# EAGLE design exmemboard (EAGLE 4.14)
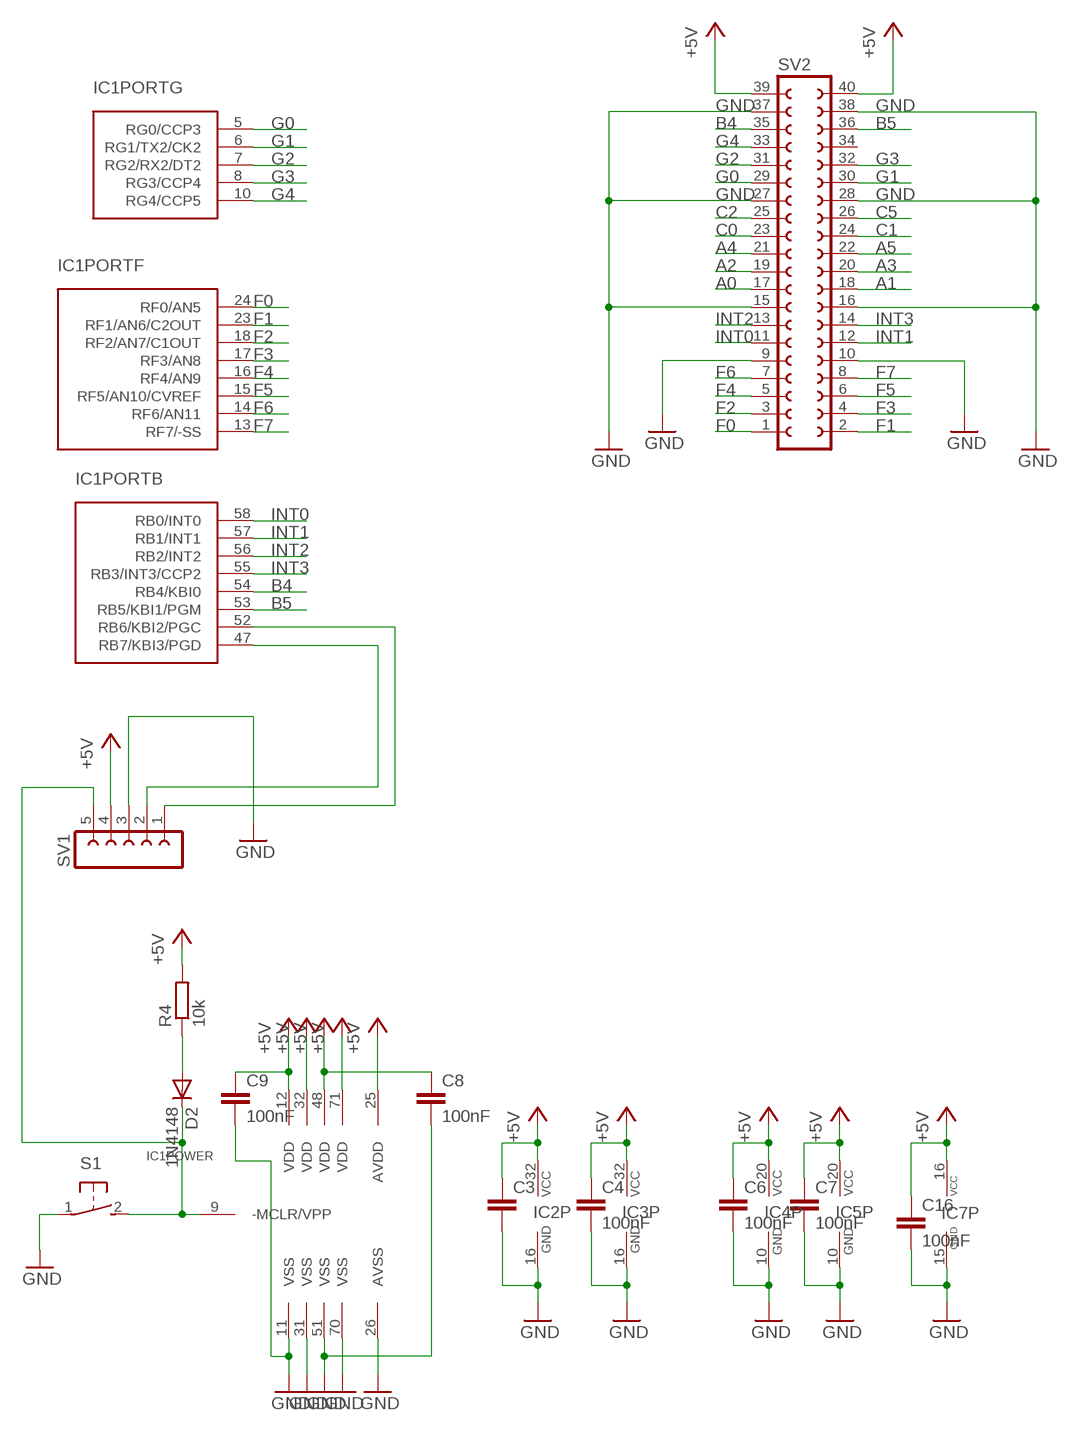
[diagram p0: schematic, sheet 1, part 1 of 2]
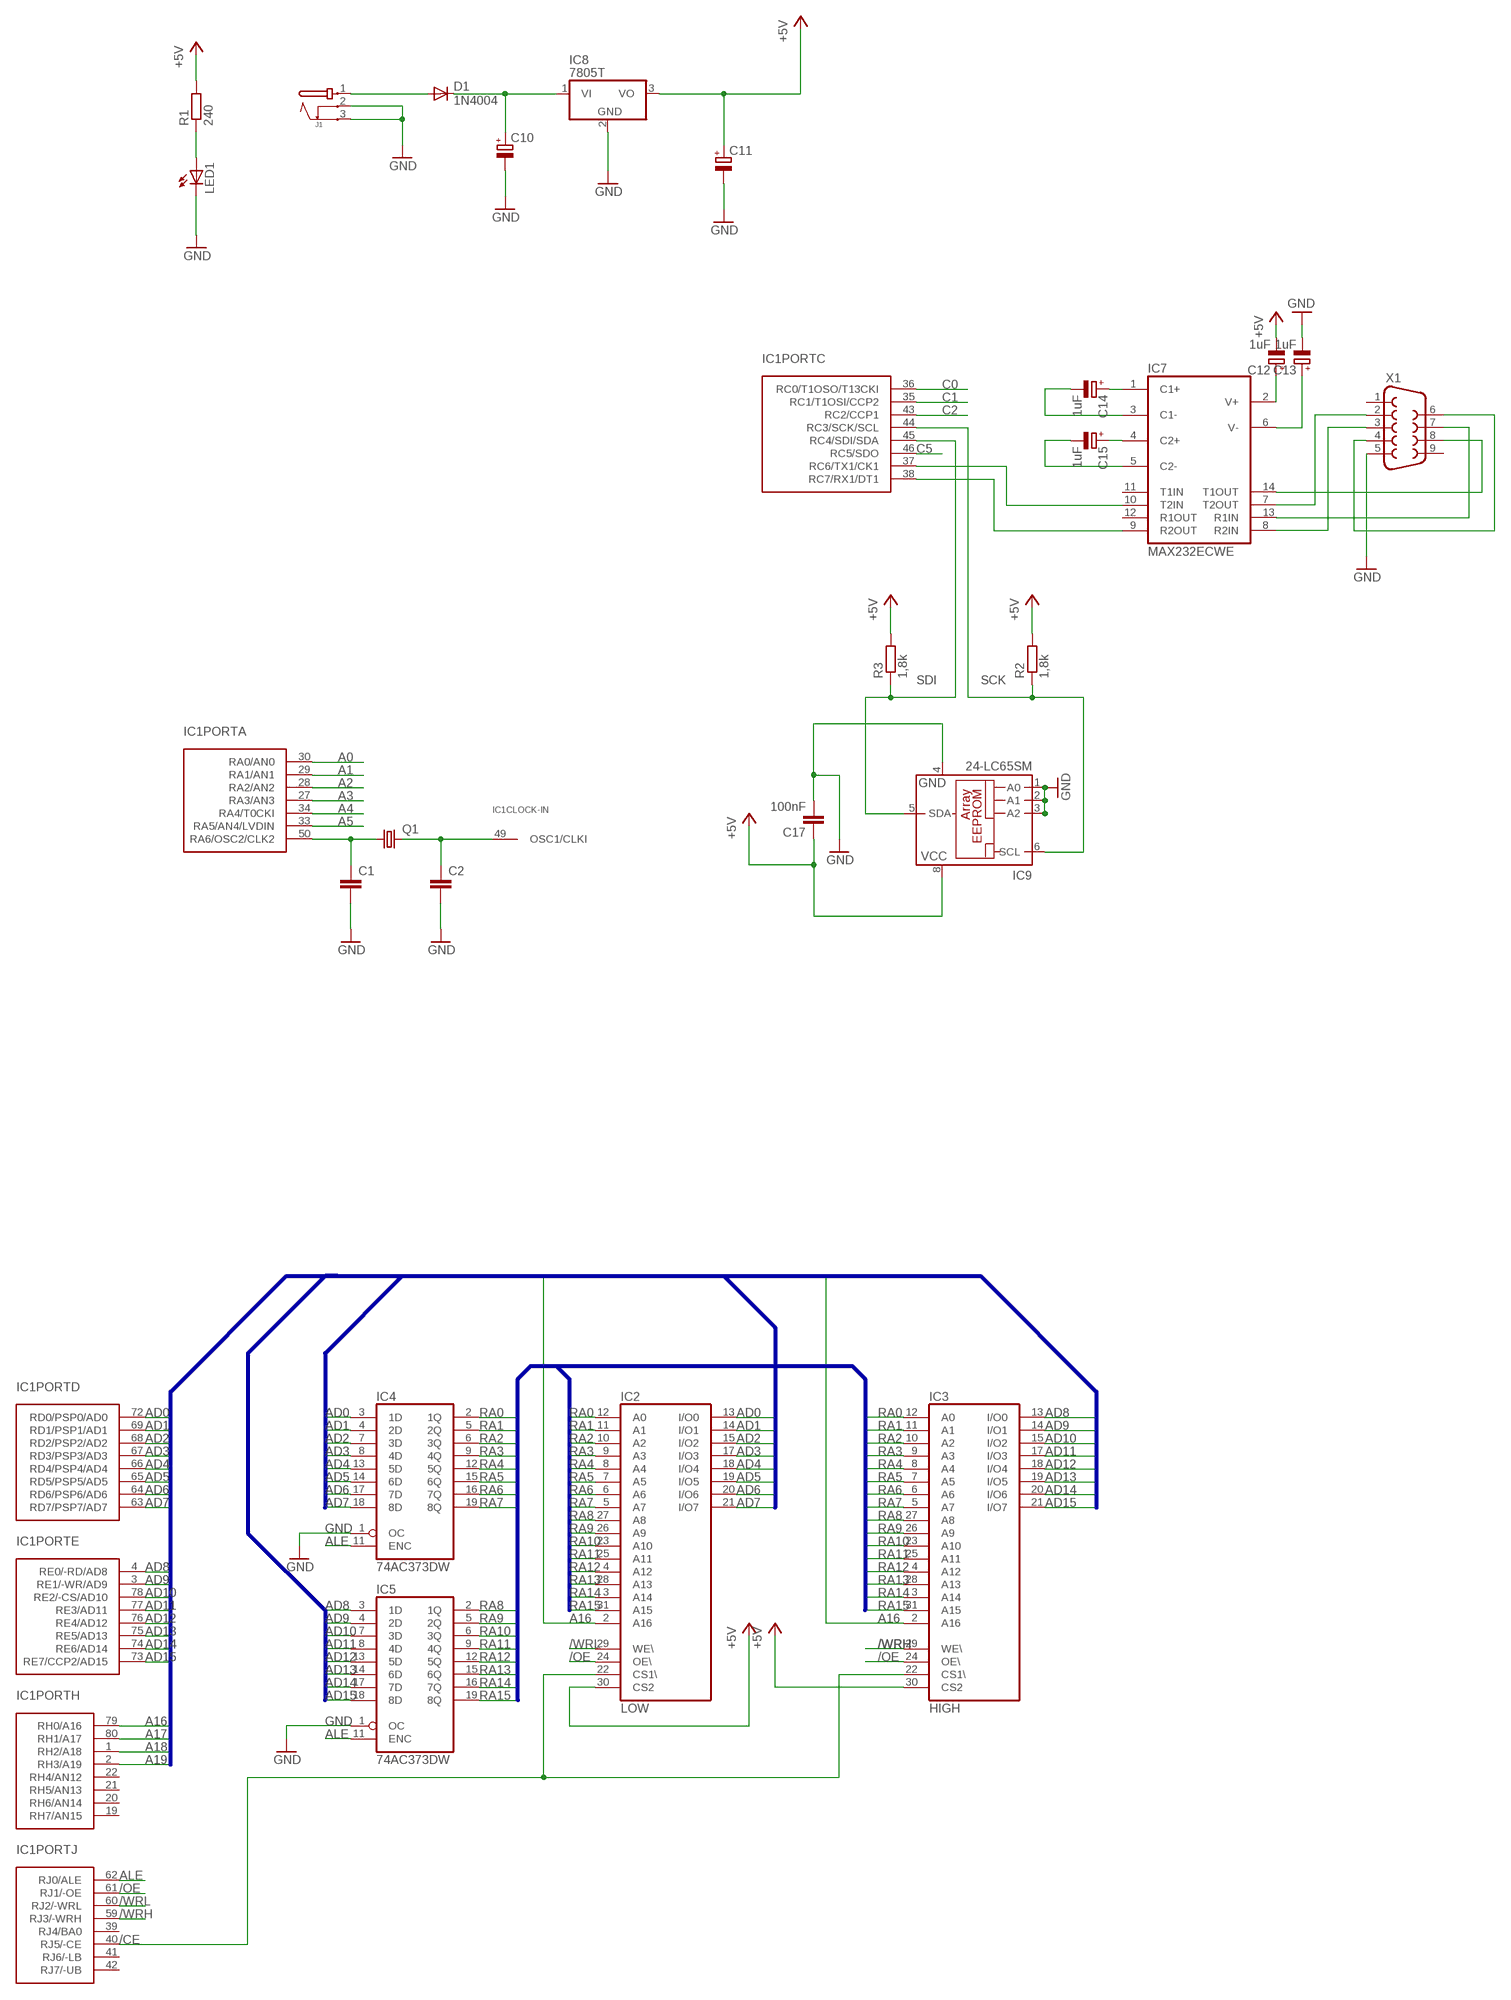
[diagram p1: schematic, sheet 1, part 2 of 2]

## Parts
C1  C-EU025-025X050  [C025-025X050]
C2  C-EU025-025X050  [C025-025X050]
C3  C-EU025-025X050  [C025-025X050]
C4  100nF  C-EU025-025X050  [C025-025X050]
C6  100nF  C-EU025-025X050  [C025-025X050]
C7  100nF  C-EU025-025X050  [C025-025X050]
C8  100nF  C-EU025-025X050  [C025-025X050]
C9  100nF  C-EU025-025X050  [C025-025X050]
C10  CPOL-EUE3.5-8  [E3,5-8]
C11  CPOL-EUE2.5-6  [E2,5-6]
C12  1uF  CPOL-EUE2-4  [E2-4]
C13  1uF  CPOL-EUE2-4  [E2-4]
C14  1uF  CPOL-EUE2-4  [E2-4]
C15  1uF  CPOL-EUE2-4  [E2-4]
C16  100nF  C-EU025-025X050  [C025-025X050]
C17  100nF  C-EU025-025X050  [C025-025X050]
D1  1N4004  [DO41-10]
D2  1N4148  [DO35-10]
IC1  PIC18F8520-I/PT  [TQFP80]
IC2  LOW  LP621024CM  [SOP32L]
IC3  HIGH  LP621024CM  [SOP32L]
IC4  74AC373DW  [SO20W]
IC5  74AC373DW  [SO20W]
IC7  MAX232ECWE  [SO16L]
IC8  7805T  [TO220H]
IC9  24-LC65SM  [SO-08M]
J1  JACK-PMS  [JACK-PMS]
LED1  LED3MM  [LED3MM]
Q1  CRYTALHC49U-V  [HC49U-V]
R1  240  R-EU_R1206  [R1206]
R2  1,8k  R-EU_R1206  [R1206]
R3  1,8k  R-EU_R1206  [R1206]
R4  10k  R-EU_R1206  [R1206]
S1  31-XX  [B3F-31XX]
SV1  FE05-1  [FE05-1]
SV2  FE20-2  [FE20-2]
X1  F09HP  [F09HP]

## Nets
+5V: C3.1 C4.1 C6.1 C7.1 C8.1 C9.1 C11.+ C12.- C16.1 C17.1 IC1.12(POWER:VDD) IC1.25(POWER:AVDD) IC1.32(POWER:VDD) IC1.48(POWER:VDD) IC1.71(POWER:VDD) IC2.30(CS2) IC2.32(VCC) IC3.30(CS2) IC3.32(VCC) IC4.20(VCC) IC5.20(VCC) IC7.16(VCC) IC8.3(VO) IC9.8(VCC) R1.2 R2.2 R3.2 R4.2 SV1.4 SV2.39 SV2.40
/CE: IC1.40(PORTJ:RJ5/-CE) IC2.22(CS1\) IC3.22(CS1\)
/OE: IC1.61(PORTJ:RJ1/-OE) IC2.24(OE\) IC3.24(OE\)
/WRH: IC1.59(PORTJ:RJ3/-WRH) IC3.29(WE\)
/WRL: IC1.60(PORTJ:RJ2/-WRL) IC2.29(WE\)
A0: IC1.30(PORTA:RA0/AN0) SV2.17
A1: IC1.29(PORTA:RA1/AN1) SV2.18
A2: IC1.28(PORTA:RA2/AN2) SV2.19
A3: IC1.27(PORTA:RA3/AN3) SV2.20
A4: IC1.34(PORTA:RA4/T0CKI) SV2.21
A5: IC1.33(PORTA:RA5/AN4/LVDIN) SV2.22
A16: IC1.79(PORTH:RH0/A16) IC2.2(A16) IC3.2(A16)
A17: IC1.80(PORTH:RH1/A17)
A18: IC1.1(PORTH:RH2/A18)
A19: IC1.2(PORTH:RH3/A19)
AD0: IC1.72(PORTD:RD0/PSP0/AD0) IC2.13(I/O0) IC4.3(1D)
AD1: IC1.69(PORTD:RD1/PSP1/AD1) IC2.14(I/O1) IC4.4(2D)
AD2: IC1.68(PORTD:RD2/PSP2/AD2) IC2.15(I/O2) IC4.7(3D)
AD3: IC1.67(PORTD:RD3/PSP3/AD3) IC2.17(I/O3) IC4.8(4D)
AD4: IC1.66(PORTD:RD4/PSP4/AD4) IC2.18(I/O4) IC4.13(5D)
AD5: IC1.65(PORTD:RD5/PSP5/AD5) IC2.19(I/O5) IC4.14(6D)
AD6: IC1.64(PORTD:RD6/PSP6/AD6) IC2.20(I/O6) IC4.17(7D)
AD7: IC1.63(PORTD:RD7/PSP7/AD7) IC2.21(I/O7) IC4.18(8D)
AD8: IC1.4(PORTE:RE0/-RD/AD8) IC3.13(I/O0) IC5.3(1D)
AD9: IC1.3(PORTE:RE1/-WR/AD9) IC3.14(I/O1) IC5.4(2D)
AD10: IC1.78(PORTE:RE2/-CS/AD10) IC3.15(I/O2) IC5.7(3D)
AD11: IC1.77(PORTE:RE3/AD11) IC3.17(I/O3) IC5.8(4D)
AD12: IC1.76(PORTE:RE4/AD12) IC3.18(I/O4) IC5.13(5D)
AD13: IC1.75(PORTE:RE5/AD13) IC3.19(I/O5) IC5.14(6D)
AD14: IC1.74(PORTE:RE6/AD14) IC3.20(I/O6) IC5.17(7D)
AD15: IC1.73(PORTE:RE7/CCP2/AD15) IC3.21(I/O7) IC5.18(8D)
ALE: IC1.62(PORTJ:RJ0/ALE) IC4.11(ENC) IC5.11(ENC)
B4: IC1.54(PORTB:RB4/KBI0) SV2.35
B5: IC1.53(PORTB:RB5/KBI1/PGM) SV2.36
C0: IC1.36(PORTC:RC0/T1OSO/T13CKI) SV2.23
C1: IC1.35(PORTC:RC1/T1OSI/CCP2) SV2.24
C2: IC1.43(PORTC:RC2/CCP1) SV2.25
C5: IC1.46(PORTC:RC5/SDO) SV2.26
F0: IC1.24(PORTF:RF0/AN5) SV2.1
F1: IC1.23(PORTF:RF1/AN6/C2OUT) SV2.2
F2: IC1.18(PORTF:RF2/AN7/C1OUT) SV2.3
F3: IC1.17(PORTF:RF3/AN8) SV2.4
F4: IC1.16(PORTF:RF4/AN9) SV2.5
F5: IC1.15(PORTF:RF5/AN10/CVREF) SV2.6
F6: IC1.14(PORTF:RF6/AN11) SV2.7
F7: IC1.13(PORTF:RF7/-SS) SV2.8
G0: IC1.5(PORTG:RG0/CCP3) SV2.29
G1: IC1.6(PORTG:RG1/TX2/CK2) SV2.30
G2: IC1.7(PORTG:RG2/RX2/DT2) SV2.31
G3: IC1.8(PORTG:RG3/CCP4) SV2.32
G4: IC1.10(PORTG:RG4/CCP5) SV2.33
GND: C1.2 C2.2 C3.2 C4.2 C6.2 C7.2 C8.2 C9.2 C10.- C11.- C13.- C16.2 C17.2 IC1.11(POWER:VSS) IC1.26(POWER:AVSS) IC1.31(POWER:VSS) IC1.51(POWER:VSS) IC1.70(POWER:VSS) IC2.16(GND) IC3.16(GND) IC4.1(OC) IC4.10(GND) IC5.1(OC) IC5.10(GND) IC7.15(GND) IC8.2(GND) IC9.1(A0) IC9.2(A1) IC9.3(A2) IC9.4(GND) J1.2 J1.3 LED1.K(C) S1.1(P) SV1.3 SV2.9 SV2.10 SV2.15 SV2.16 SV2.27 SV2.28 SV2.37 SV2.38 X1.5
INT0: IC1.58(PORTB:RB0/INT0) SV2.11
INT1: IC1.57(PORTB:RB1/INT1) SV2.12
INT2: IC1.56(PORTB:RB2/INT2) SV2.13
INT3: IC1.55(PORTB:RB3/INT3/CCP2) SV2.14
N$2: C1.1 IC1.50(PORTA:RA6/OSC2/CLK2) Q1.1
N$3: C2.1 IC1.49(CLOCK-IN:OSC1/CLKI) Q1.2
N$4: LED1.A R1.1
N$5: C14.+ IC7.1(C1+)
N$6: IC1.38(PORTC:RC7/RX1/DT1) IC7.9(R2OUT)
N$7: IC1.37(PORTC:RC6/TX1/CK1) IC7.10(T2IN)
N$8: IC7.14(T1OUT) X1.8
N$9: IC7.8(R2IN) X1.3
N$10: IC7.7(T2OUT) X1.2
N$11: X1.4 X1.6
N$12: C14.- IC7.3(C1-)
N$13: IC7.13(R1IN) X1.7
N$14: C15.+ IC7.4(C2+)
N$15: C15.- IC7.5(C2-)
N$16: C12.+ IC7.2(V+)
N$17 [+5V]: D1.A J1.1
N$18 [+5V]: C10.+ D1.C IC8.1(VI)
N$19: C13.+ IC7.6(V-)
N$20: D2.A R4.1
N$22: IC1.52(PORTB:RB6/KBI2/PGC) SV1.1
N$23: IC1.47(PORTB:RB7/KBI3/PGD) SV1.2
N$24: D2.C IC1.9(POWER:-MCLR/VPP) S1.2(S) SV1.5
RA0: IC2.12(A0) IC3.12(A0) IC4.2(1Q)
RA1: IC2.11(A1) IC3.11(A1) IC4.5(2Q)
RA2: IC2.10(A2) IC3.10(A2) IC4.6(3Q)
RA3: IC2.9(A3) IC3.9(A3) IC4.9(4Q)
RA4: IC2.8(A4) IC3.8(A4) IC4.12(5Q)
RA5: IC2.7(A5) IC3.7(A5) IC4.15(6Q)
RA6: IC2.6(A6) IC3.6(A6) IC4.16(7Q)
RA7: IC2.5(A7) IC3.5(A7) IC4.19(8Q)
RA8: IC2.27(A8) IC3.27(A8) IC5.2(1Q)
RA9: IC2.26(A9) IC3.26(A9) IC5.5(2Q)
RA10: IC2.23(A10) IC3.23(A10) IC5.6(3Q)
RA11: IC2.25(A11) IC3.25(A11) IC5.9(4Q)
RA12: IC2.4(A12) IC3.4(A12) IC5.12(5Q)
RA13: IC2.28(A13) IC3.28(A13) IC5.15(6Q)
RA14: IC2.3(A14) IC3.3(A14) IC5.16(7Q)
RA15: IC2.31(A15) IC3.31(A15) IC5.19(8Q)
SCK: IC1.44(PORTC:RC3/SCK/SCL) IC9.6(SCL) R2.1
SDI: IC1.45(PORTC:RC4/SDI/SDA) IC9.5(SDA) R3.1
Unconnected: IC1.19(PORTH:RH7/AN15) IC1.20(PORTH:RH6/AN14) IC1.21(PORTH:RH5/AN13) IC1.22(PORTH:RH4/AN12) IC1.39(PORTJ:RJ4/BA0) IC1.41(PORTJ:RJ6/-LB) IC1.42(PORTJ:RJ7/-UB) IC2.1(NC) IC3.1(NC) IC7.11(T1IN) IC7.12(R1OUT) SV2.34 X1.1 X1.9

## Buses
B$1
B$2

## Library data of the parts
C1-C4 C6-C9 C16 C17 = rcl:C-EU: CAPACITOR, European symbol
C10-C15 = rcl:CPOL-EU: POLARIZED CAPACITOR, European symbol
D1 = diode:1N4004: DIODE
D2 = diode:1N4148: DIODE
IC1 = pic18fxx20-fxx8:PIC18F8*20: 80-Pin High Performance, 1 Mbit Enhanced FLASH Microcontrollers with A/D and expansion bus DEVICE DIFFERENCES Feature PIC18F8520 PIC18F8620 PIC18F8720 On-chip Program Memory (Kbytes) 32 64 128 Data Memory (bytes) 2048 3840 3840 Boot Block (bytes) 2048 512 512 Timer1 Low Power Option Yes No No I/O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
IC2 IC3 = memory:LP621024CM: MEMORY
IC4 IC5 = 74xx-eu:74*373: Octal D type transparent LATCH, edge triggered
IC7 = maxim:MAX232ECWE: RS232 TRANSEIVER
IC8 = linear:78*: Positive VOLTAGE REGULATOR Source: http://cache.national.com/ds/LM/LM78L05.pdf http://www.fairchildsemi.com/ds/LM/LM7805.pdf
IC9 = microchip:24-*: Serial EEPROM 32 K/64 K, 1.8 V, I2C
J1 = POWER-IN:JACK-PMS
LED1 = led:LED: LED
Q1 = crystal:CRYTAL: CRYSTAL
R1-R4 = rcl:R-EU_: RESISTOR, European symbol
S1 = switch-omron:31-XX: OMRON SWITCH
SV1 = con-lsta:FE05-1: FEMALE HEADER
SV2 = con-lsta:FE20-2: FEMALE HEADER
X1 = con-subd:F09: SUB-D

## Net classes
0 default: width 0.254 mm
1 +5V: width 0.305 mm

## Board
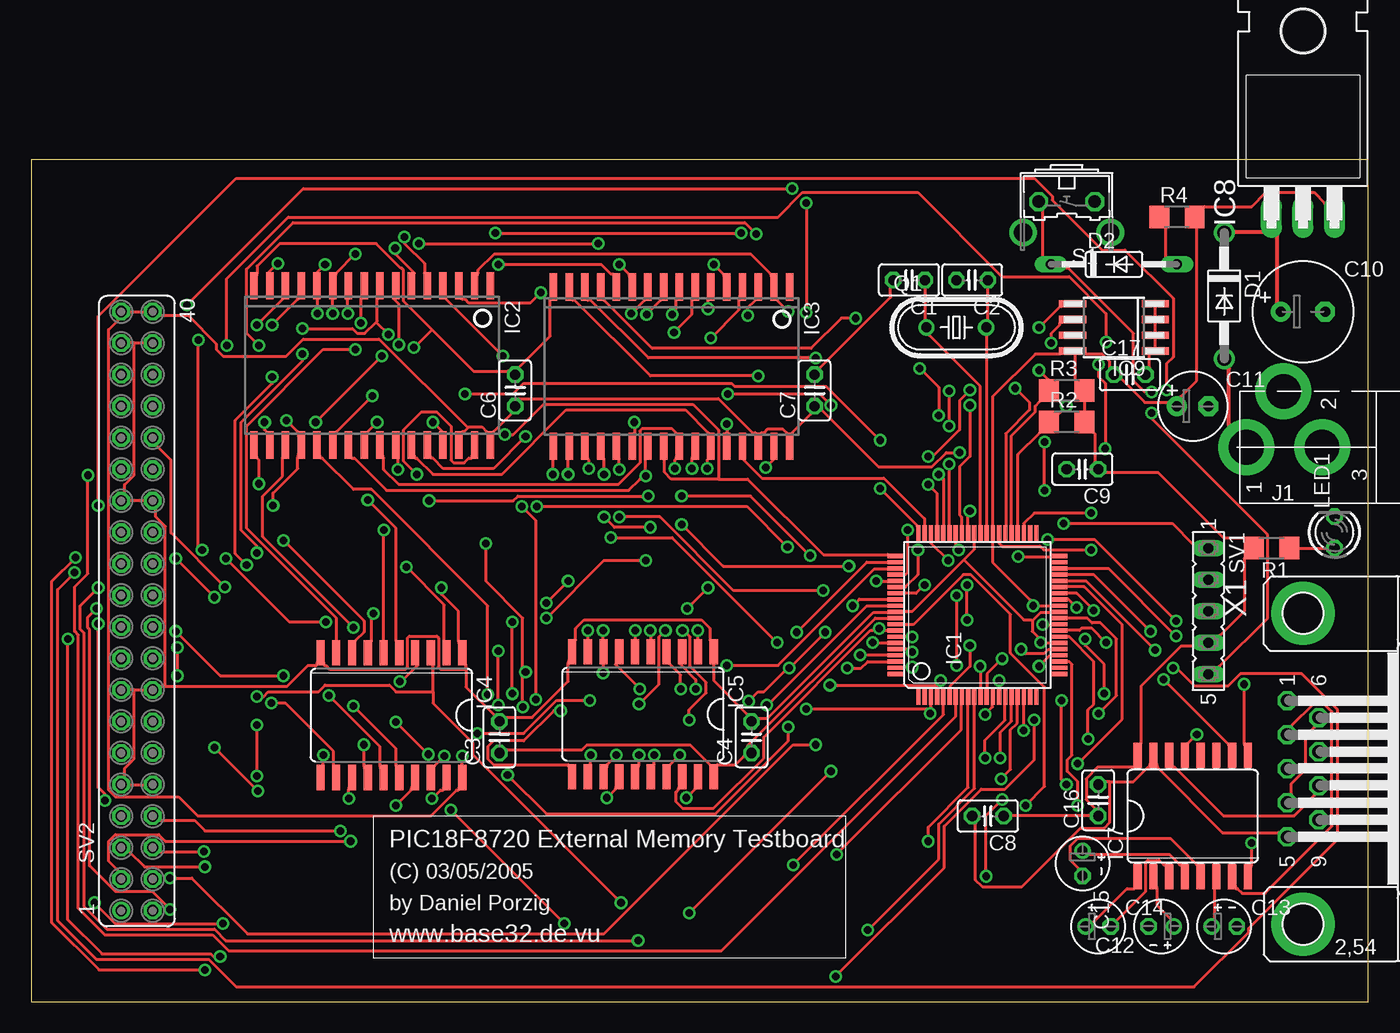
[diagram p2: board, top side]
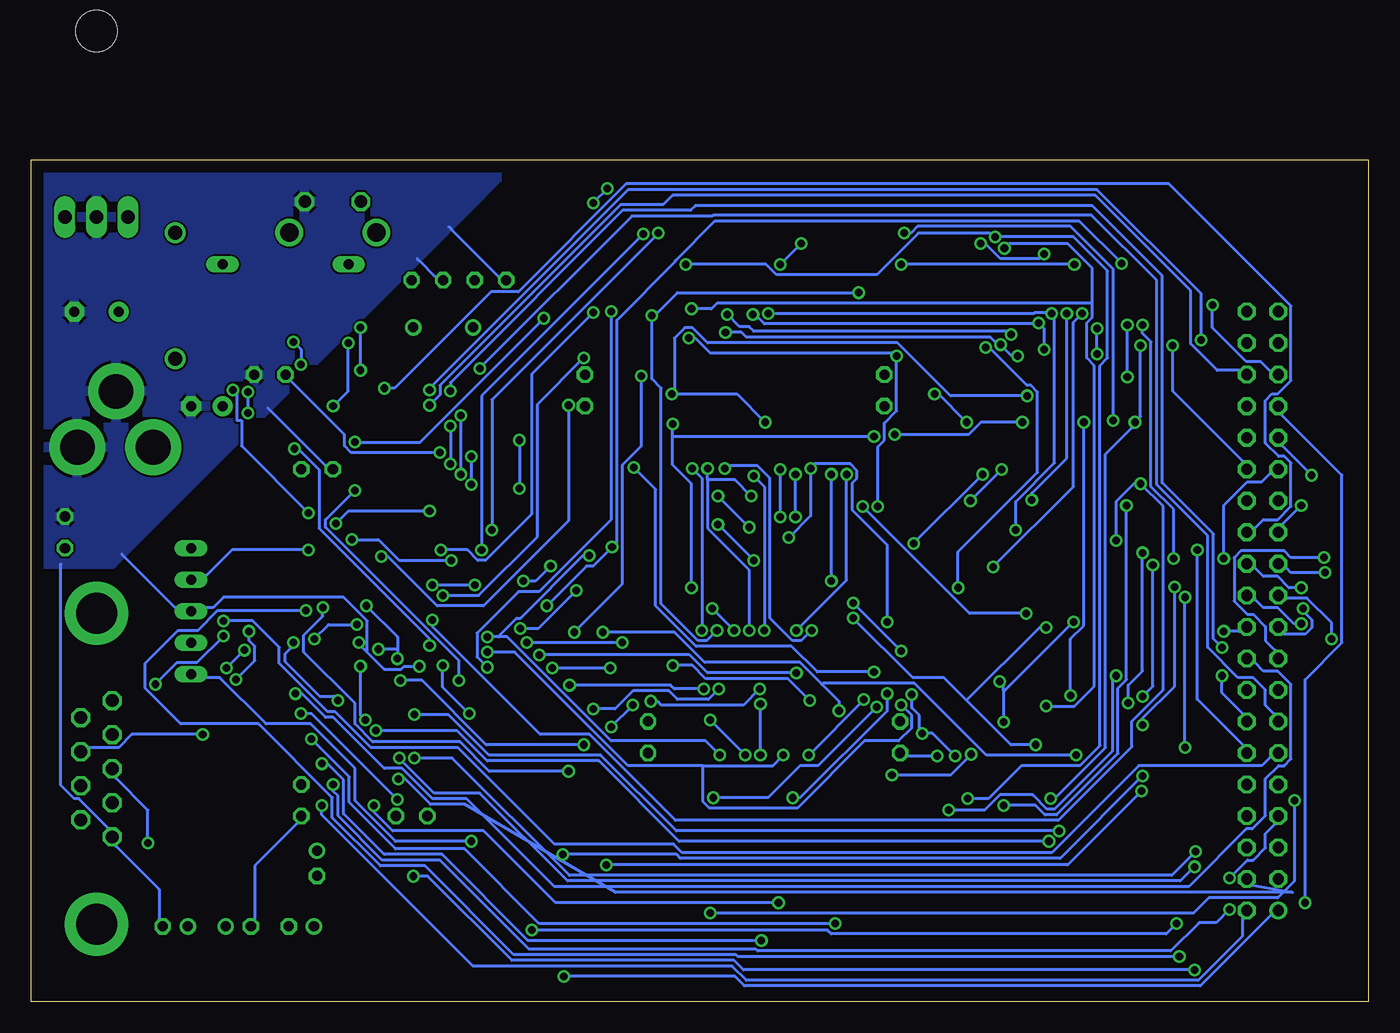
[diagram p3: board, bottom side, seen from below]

Size 107.8 x 67.86 mm. Coordinates in mm from the lower left corner, seen from the top.
Outline: 0,0.02 107.8,0 107.8,67.85 0,67.86 0,0.02
Copper layers (1*16): Top 0.035mm / dielectric 1.5mm / Bottom 0.035mm
Design rules "default": minimum track width 10mil, minimum drill 24mil, track to track 6mil, track to pad 6mil, pad to pad 6mil, via to via 6mil, smd to smd 0mil, copper to edge 40mil, drill to drill 8mil, minimum pad ring 10mil, minimum via ring 8mil, stop-mask expansion 4mil, vias tented up to drill 0mil, thermal gap 10mil

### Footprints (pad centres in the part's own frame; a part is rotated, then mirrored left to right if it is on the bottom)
C025-025X050 = drill 0.813 octagon: 1 -1.27,0; 2 1.27,0
E3,5-8 = drill 0.813 pad 1.6 round: + -1.778,0 | drill 0.813 pad 1.6 octagon: - 1.778,0
E2,5-6 = drill 0.813 pad 1.6 round: + -1.27,0 | drill 0.813 pad 1.6 octagon: - 1.27,0
E2-4 = drill 0.813 pad 1.27 round: + -1.016,0 | drill 0.813 pad 1.27 octagon: - 1.016,0
DO41-10 = drill 1.118 round: A 5.08,0; C -5.08,0
DO35-10 = drill 0.813 long: A 5.08,0; C -5.08,0
TQFP80 = smd 1.3 x 0.35: 1 -6.595,4.75; 2 -6.595,4.25; 3 -6.595,3.75; 4 -6.595,3.25; 5 -6.595,2.75; 6 -6.595,2.25; 7 -6.595,1.75; 8 -6.595,1.25; 9 -6.595,0.75; 10 -6.595,0.25; 11 -6.595,-0.25; 12 -6.595,-0.75; 13 -6.595,-1.25; 14 -6.595,-1.75; 15 -6.595,-2.25; 16 -6.595,-2.75; 17 -6.595,-3.25; 18 -6.595,-3.75; 19 -6.595,-4.25; 20 -6.595,-4.75; 41 6.595,-4.75; 42 6.595,-4.25; 43 6.595,-3.75; 44 6.595,-3.25; 45 6.595,-2.75; 46 6.595,-2.25; 47 6.595,-1.75; 48 6.595,-1.25; 49 6.595,-0.75; 50 6.595,-0.25; 51 6.595,0.25; 52 6.595,0.75; 53 6.595,1.25; 54 6.595,1.75; 55 6.595,2.25; 56 6.595,2.75; 57 6.595,3.25; 58 6.595,3.75; 59 6.595,4.25; 60 6.595,4.75 | smd 0.35 x 1.3: 21 -4.75,-6.595; 22 -4.25,-6.595; 23 -3.75,-6.595; 24 -3.25,-6.595; 25 -2.75,-6.595; 26 -2.25,-6.595; 27 -1.75,-6.595; 28 -1.25,-6.595; 29 -0.75,-6.595; 30 -0.25,-6.595; 31 0.25,-6.595; 32 0.75,-6.595; 33 1.25,-6.595; 34 1.75,-6.595; 35 2.25,-6.595; 36 2.75,-6.595; 37 3.25,-6.595; 38 3.75,-6.595; 39 4.25,-6.595; 40 4.75,-6.595; 61 4.75,6.595; 62 4.25,6.595; 63 3.75,6.595; 64 3.25,6.595; 65 2.75,6.595; 66 2.25,6.595; 67 1.75,6.595; 68 1.25,6.595; 69 0.75,6.595; 70 0.25,6.595; 71 -0.25,6.595; 72 -0.75,6.595; 73 -1.25,6.595; 74 -1.75,6.595; 75 -2.25,6.595; 76 -2.75,6.595; 77 -3.25,6.595; 78 -3.75,6.595; 79 -4.25,6.595; 80 -4.75,6.595
SOP32L = smd 0.6 x 2.2: 1 -9.525,-6.416; 2 -8.255,-6.416; 3 -6.985,-6.416; 4 -5.715,-6.416; 5 -4.445,-6.416; 6 -3.175,-6.416; 7 -1.905,-6.416; 8 -0.635,-6.416; 9 0.635,-6.416; 10 1.905,-6.416; 11 3.175,-6.416; 12 4.445,-6.416; 13 5.715,-6.416; 14 6.985,-6.416; 15 8.255,-6.416; 16 9.525,-6.416; 17 9.525,6.416; 18 8.255,6.416; 19 6.985,6.416; 20 5.715,6.416; 21 4.445,6.416; 22 3.175,6.416; 23 1.905,6.416; 24 0.635,6.416; 25 -0.635,6.416; 26 -1.905,6.416; 27 -3.175,6.416; 28 -4.445,6.416; 29 -5.715,6.416; 30 -6.985,6.416; 31 -8.255,6.416; 32 -9.525,6.416
SO20W = smd 0.66 x 2.032: 1 -5.715,-5.029; 2 -4.445,-5.029; 3 -3.175,-5.029; 4 -1.905,-5.029; 5 -0.635,-5.029; 6 0.635,-5.029; 7 1.905,-5.029; 8 3.175,-5.029; 9 4.445,-5.029; 10 5.715,-5.029; 11 5.715,5.029; 12 4.445,5.029; 13 3.175,5.029; 14 1.905,5.029; 15 0.635,5.029; 16 -0.635,5.029; 17 -1.905,5.029; 18 -3.175,5.029; 19 -4.445,5.029; 20 -5.715,5.029
SO16L = smd 0.66 x 2.032: 1 -4.445,-4.902; 2 -3.175,-4.902; 3 -1.905,-4.902; 4 -0.635,-4.902; 5 0.635,-4.902; 6 1.905,-4.902; 7 3.175,-4.902; 8 4.445,-4.902; 9 4.445,4.902; 10 3.175,4.902; 11 1.905,4.902; 12 0.635,4.902; 13 -0.635,4.902; 14 -1.905,4.902; 15 -3.175,4.902; 16 -4.445,4.902
TO220H = drill 1.118 long: 1 -2.54,-10.16; 2 0,-10.16; 3 2.54,-10.16 | hole 3.302: 0,4.826
SO-08M = smd 0.6 x 2.2: 1 -1.905,-3.33; 2 -0.635,-3.33; 3 0.635,-3.33; 4 1.905,-3.33; 5 1.905,3.33; 6 0.635,3.33; 7 -0.635,3.33; 8 -1.905,3.33
JACK-PMS = drill 2.8 pad 4.5 round: 1 -0.5,-3.31; 2 -5,-0.31; 3 -0.5,2.809
LED3MM = drill 0.813 octagon: A -1.27,0; K 1.27,0
HC49U-V = drill 0.813 round: 1 -2.413,0; 2 2.413,0
R1206 = smd 1.6 x 1.803: 1 -1.422,0; 2 1.422,0
B3F-31XX = drill 1.016 octagon: 1 -2.261,-1.245; 2 2.261,-1.245 | drill 1.499 pad 2.159 round: 3 -3.505,1.245; 4 3.505,1.245
FE05-1 = drill 0.813 long: 1 -5.08,0; 2 -2.54,0; 3 0,0; 4 2.54,0; 5 5.08,0
FE20-2 = drill 0.914 round: 1 -24.13,1.27 | drill 0.914 octagon: 2 -24.13,-1.27; 3 -21.59,1.27; 4 -21.59,-1.27; 5 -19.05,1.27; 6 -19.05,-1.27; 7 -16.51,1.27; 8 -16.51,-1.27; 9 -13.97,1.27; 10 -13.97,-1.27; 11 -11.43,1.27; 12 -11.43,-1.27; 13 -8.89,1.27; 14 -8.89,-1.27; 15 -6.35,1.27; 16 -6.35,-1.27; 17 -3.81,1.27; 18 -3.81,-1.27; 19 -1.27,1.27; 20 -1.27,-1.27; 21 1.27,1.27; 22 1.27,-1.27; 23 3.81,1.27; 24 3.81,-1.27; 25 6.35,1.27; 26 6.35,-1.27; 27 8.89,1.27; 28 8.89,-1.27; 29 11.43,1.27; 30 11.43,-1.27; 31 13.97,1.27; 32 13.97,-1.27; 33 16.51,1.27; 34 16.51,-1.27; 35 19.05,1.27; 36 19.05,-1.27; 37 21.59,1.27; 38 21.59,-1.27; 39 24.13,1.27; 40 24.13,-1.27
F09HP = drill 1.016 octagon: 1 -5.486,-1.27; 2 -2.743,-1.27; 3 0,-1.27; 4 2.743,-1.27; 5 5.486,-1.27; 6 -4.115,1.27; 7 -1.372,1.27; 8 1.372,1.27; 9 4.115,1.27 | drill 3.302 pad 5.08 round: G1 -12.522,0; G2 12.522,0

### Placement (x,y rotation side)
C1  70.77,58.16 180 top
C2  75.85,58.16 180 top
C3  37.75,21.33 90 top
C4  58.07,21.33 90 top
C6  39.02,49.27 90 top
C7  63.15,49.27 90 top
C8  77.12,14.98 180 top
C9  84.74,42.92 180 top
C10  102.52,55.62 0 top
C11  93.63,48 0 top
C12  91.09,6.09 180 top
C13  96.17,6.09 0 top
C14  86.01,6.09 0 top
C15  84.74,11.17 270 top
C16  86.01,16.25 90 top
C17  88.55,50.54 0 top
D1  96.17,56.89 270 top
D2  87.28,59.43 0 top
IC1  76.28,31.17 90 top
IC2  27.49,51.28 180 top
IC3  51.63,51.19 180 top
IC4  29.05,23.1 180 top
IC5  49.32,23.17 180 top
IC7  93.63,14.98 0 top
IC8  102.52,73.4 0 top
IC9  87.28,54.35 90 top
J1  101.25,44.19 270 top
LED1  105.06,37.84 90 top
Q1  74.58,54.35 0 top
R1  99.98,36.57 180 top
R2  83.47,46.73 0 top
R3  83.47,49.27 0 top
R4  92.36,63.24 0 top
S1  83.47,63.24 180 top
SV1  94.9,31.49 270 top
SV2  8.54,31.49 90 top
X1  102.52,18.79 270 top

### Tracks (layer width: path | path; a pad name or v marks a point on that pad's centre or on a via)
+5V  (via drill 0.61)
  Top 0.254: C8.1 79.02,15 85.43,15 C16.1 85.73,15.61 85.04,16.3 85.04,17.97 85.96,18.89 88.93,18.89 IC7.16 89.46,20.87 89.46,25.44 92.66,28.64 93.65,28.64 SV1.4 95.86,29.56 97.77,31.46 97.77,35.73 R1.2 97.77,37.4 96.09,37.4 90.84,42.66 86.64,42.66 C9.1 85.73,43.5 85.73,45.79 85.65,45.86 R2.2 84.89,47.61 84.89,48.38 R3.2 84.13,50.13 84.13,52.19 IC9.8 | v78.26,27.65 77.04,26.43 77.04,25.21 IC1.12 | IC1.32 82.22,31.92 v80.78,31.92 80.55,32.37 77.5,35.42 77.5,37.18 IC1.48 77.5,38.39 77.5,48.76 80.93,52.19 82.91,52.19 IC9.8 | v79.79,28.41 80.09,28.11 81.69,28.11 82,28.41 82.22,28.41 IC1.25 | IC8.3 104.25,64.38 103.41,65.22 99.52,65.22 98.38,64.07 94.57,64.07 R4.2 93.96,62.4 93.96,50.05 92.66,48.76 C11.+ 91.6,48.3 89.77,48.3 87.86,50.21 C17.1 86.95,51.12 86.95,51.58 86.34,52.19 85.04,52.19 IC9.8 | v34.75,19.8 34.75,19.04 IC4.20 34.45,17.06 34.3,17.06 32.24,15 13.42,15 11.89,16.52 6.79,16.52 6.25,17.06 6.25,54.17 7.02,54.93 SV2.39 SV2.40 10.44,55.31 12.65,55.31 14.94,53.02 14.94,52.57 15.47,52.03 20.58,52.03 21.95,53.41 28.05,53.41 35.21,46.24 | IC1.71 69.04,30.93 68.05,30.93 57.76,20.64 C4.1 57.46,19.8 56.77,19.12 55.33,19.12 IC5.20 54.72,19.12 53.12,20.72 44.81,20.72 44.43,20.33 38.33,20.33 C3.1 | 35.21,46.24 35.29,46.32 36.35,46.32 36.73,45.94 IC2.32 37.27,45.94 38.71,47.39 C6.1 39.32,48.61 55.4,48.61 58.15,45.86 58.37,45.86 IC3.30 58.91,45.86 59.06,45.86 59.36,46.17 60.58,46.17 60.89,45.86 IC3.32 61.35,45.86 62.87,47.39 C7.1 63.71,47.69 68.28,43.12 72.62,43.12 73.77,44.26 v74.83,44.26 | 35.21,46.24 34.9,45.94 34.75,45.94 IC2.30
  Bottom 0.254: C12.- 89.77,6.7 89.77,10.96 86.34,14.39 C16.1 | 78.26,28.41 78.26,29.4 v80.78,31.92 | 78.26,28.41 v78.26,27.65 | 78.26,28.41 v79.79,28.41 | v34.75,19.8 37.11,19.8 C3.1 | v74.83,44.26 82,44.26 82.53,44.8 82.53,45.71 86.87,50.05 C17.1
/CE  (via drill 0.61)
  Top 0.254: v79.56,35.88 82.22,35.88 IC1.40 | v64.47,48.07 63.56,48.99 v56.16,48.99 | v48.62,46.7 48.62,45.86 IC3.22 | v27.51,48.83 24.62,45.94 IC2.22
  Bottom 0.254: v79.56,35.88 79.02,35.88 75.06,31.92 71.33,31.92 64.47,38.78 v64.47,48.07 | v48.62,46.7 50.91,48.99 v56.16,48.99 55.94,49.44 55.94,53.48 55.1,54.32 54.49,54.32 53.27,53.1 37.95,53.1 33.69,48.83 v27.51,48.83
/OE  (via drill 0.61)
  Top 0.254: 55.4,42.13 51.59,42.13 51.06,42.66 51.06,43.73 IC3.24 | 55.4,42.13 57.76,42.13 63.86,36.03 69.04,36.03 IC1.61 | v27.89,46.7 27.13,45.94 IC2.24 | v38.18,45.71 38.87,45.71 41.31,48.15 53.35,48.15 55.4,46.09 55.4,42.13
  Bottom 0.254: v27.89,46.7 31.25,46.7 32.24,45.71 v38.18,45.71
/WRH
  Top 0.254: IC1.59 72.01,38.39 72.01,38.93 68.74,42.2 58.91,42.2 57.38,43.73 IC3.29
/WRL  (via drill 0.61)
  Top 0.254: v68.43,41.37 71.4,38.39 IC1.60 | v68.43,45.25 64.09,49.6 56.7,49.6 56.47,49.82 39.71,49.82 38.87,48.99 v34.98,48.99 | v32.39,46.7 33.15,45.94 IC2.29
  Bottom 0.254: v68.43,45.25 v68.43,41.37 | v34.98,48.99 34.68,48.99 v32.39,46.7
A0  (via drill 0.61)
  Top 0.254: v86.03,23.23 87.48,24.68 87.48,29.25 86.19,30.55 85.5,30.55 85.12,30.93 83.52,30.93 IC1.30 | v78.26,16.3 76.97,15 v76.97,10.12 | v14.03,2.58 5.49,2.58 1.68,6.39 1.68,33.9 v3.59,35.8
  Bottom 0.254: v86.03,23.23 85.2,23.23 v78.26,16.3 | v76.97,10.12 75.82,10.12 69.04,3.34 51.14,3.34 50.37,2.58 v14.03,2.58 | v3.59,35.8 6.25,35.8 6.79,36.34 10.29,36.34 10.83,35.8 10.83,32.3 9.76,31.23 9.3,31.23 8.31,30.24 8.31,29.1 7.55,28.34 SV2.17
A1  (via drill 0.61)
  Top 0.254: v81.54,30.39 82.22,30.39 IC1.29 | v84.97,29.25 84.97,28.72 86.49,27.19 v86.49,24.83
  Bottom 0.254: v81.54,30.39 83.83,30.39 v84.97,29.25 | v86.49,24.83 85.96,24.83 84.05,22.93 83.44,22.93 79.33,18.81 77.88,18.81 75.44,16.37 72.7,16.37 65.61,9.29 14.48,9.29 9.83,13.93 9.38,13.93 8.31,15 8.31,17.97 7.24,19.04 6.79,19.04 6.25,19.57 6.25,25.59 7.32,26.66 8.46,26.66 9.15,27.35 SV2.18
A2  (via drill 0.61)
  Top 0.254: v86.64,28.95 85.5,30.09 84.66,30.09 84.51,29.94 83.52,29.94 IC1.28 | v83.06,24.3 83.06,17.9 v83.44,17.52 | v11.21,7.46 9.76,8.9 6.79,8.9 4.73,10.96 4.73,30.01 4.58,30.16 4.58,31 v5.26,31.69
  Bottom 0.254: v86.64,28.95 86.64,28.72 87.33,28.03 87.33,27.42 84.51,24.6 83.37,24.6 v83.06,24.3 | v83.44,17.52 83.44,16.98 83.06,16.6 83.06,15 79.48,11.42 74.83,11.42 67.67,4.26 49.38,4.26 49.23,4.1 15.93,4.1 13.64,6.39 12.27,6.39 v11.21,7.46 | v5.26,31.69 5.26,31.46 4.58,30.77 4.58,30.16 5.11,29.63 6.86,29.63 SV2.19
A3  (via drill 0.61)
  Top 0.254: v85.2,21.17 85.2,23.54 85.65,23.99 85.65,27.42 83.67,29.4 83.52,29.4 IC1.27 | v33.84,15.46 v42.98,6.31 | v20.35,26.28 15.25,26.28 v11.66,29.86
  Bottom 0.254: v85.2,21.17 82.15,18.13 82.15,16.07 78.41,12.33 72.85,12.33 66.83,6.31 v42.98,6.31 | v33.84,15.46 30.94,15.46 29.72,16.68 27.06,16.68 25.91,15.53 25.3,15.53 20.66,20.18 20.66,25.97 v20.35,26.28 | v11.66,29.86 10.44,29.86 SV2.20
A4  (via drill 0.61)
  Top 0.254: v85.65,31.54 84.28,32.91 83.52,32.91 IC1.34 | v15.25,3.65 14.71,3.65 14.48,3.88 5.72,3.88 2.98,6.62 v2.98,29.25
  Bottom 0.254: v85.65,31.54 92.74,31.54 94.34,29.94 95.94,29.94 98.61,27.27 98.61,25.29 95.71,22.39 89.46,22.39 83.52,16.45 83.52,14.85 79.63,10.96 76.05,10.96 68.89,3.8 50.98,3.8 50.83,3.65 v15.25,3.65 | v2.98,29.25 2.98,30.55 4.96,32.53 6.63,32.53 SV2.21
A5  (via drill 0.61)
  Top 0.254: v84.28,31.76 83.6,32.45 83.52,32.45 IC1.33 | v53.04,7.15 v64.47,18.58 | v5.95,16.22 5.95,16.75 5.42,17.29 v5.42,30.47
  Bottom 0.254: v84.28,31.76 84.28,31.08 85.81,29.56 85.81,28.18 81.69,24.07 81.69,22.39 80.24,20.94 73.23,20.94 70.87,18.58 v64.47,18.58 | v53.04,7.15 14.1,7.15 12.88,8.37 7.32,8.37 5.95,9.74 v5.95,16.22 | v5.42,30.47 6.02,30.47 7.32,31.76 8.46,31.76 9.15,32.45 SV2.22
A16  (via drill 0.61)
  Top 0.254: v71.02,26.96 70.26,26.96 IC1.79 | v61.04,55.62 60.13,56.53 IC3.2 59.59,58.66 57.99,60.26 37.34,60.26 36.05,58.97 36.05,58.74 IC2.2
  Bottom 0.254: v71.02,26.96 71.86,27.8 71.86,29.71 68.51,33.06 66.83,33.06 61.04,38.85 v61.04,55.62
AD0  (via drill 0.61)
  Top 0.254: v80.17,15.84 81.69,17.36 81.69,25.36 78.95,28.11 78.95,31.23 75.75,34.43 75.14,34.43 71.1,30.39 70.26,30.39 IC1.72 | v47.55,7.99 35.59,19.95 35.59,20.87 32.39,24.07 32.39,24.98 | 32.39,24.98 32.39,27.12 IC4.3 | v19.44,54.55 21.49,56.61 IC2.13 | v19.44,50.36 19.44,49.82 16.46,46.85 16.46,36.11 v17.38,35.19 | v18.22,24.6 18.75,24.6 19.13,24.98 23.17,24.98 23.7,25.52 28.88,25.52 29.42,24.98 32.39,24.98
  Bottom 0.254: v80.17,15.84 80.17,15.31 78.64,13.78 71.33,13.78 65.54,7.99 v47.55,7.99 | v19.44,50.36 v19.44,54.55 | v17.38,35.19 17.38,25.44 v18.22,24.6
AD1  (via drill 0.61)
  Top 0.254: v59.29,23.92 59.36,23.92 67.37,31.92 69.04,31.92 IC1.69 | v61.04,22.16 61.04,21.02 55.17,15.15 41.53,15.15 v38.41,18.28 | v29.42,22.54 v32.01,19.95 | v29.72,25.82 29.88,25.82 31.17,27.12 IC4.4 | v18.22,54.55 20.27,56.61 IC2.14 | v15.7,35.73 20.81,30.62 v23.78,30.62
  Bottom 0.254: v61.04,22.16 v59.29,23.92 | v38.41,18.28 33.69,18.28 v32.01,19.95 | 29.42,25.06 29.42,25.52 v29.72,25.82 | 29.42,25.06 v29.42,22.54 | v18.22,54.55 18.22,53.86 17.53,53.18 17.53,41.52 15.7,39.69 v15.7,35.73 | v23.78,30.62 29.34,25.06 29.42,25.06
AD2  (via drill 0.61)
  Top 0.254: v66.22,31.92 66.76,32.45 69.04,32.45 IC1.68 | v19.89,59.5 19.13,58.74 IC2.15 | v27.59,31.31 27.44,31.16 27.44,29.1 IC4.7 | v40.77,39.92 57.69,39.92 v60.97,36.64
  Bottom 0.254: v66.22,31.92 63.02,35.12 62.49,35.12 v60.97,36.64 60.58,37.02 60.58,54.93 55.86,59.65 55.86,59.73 52.66,62.93 23.32,62.93 v19.89,59.5 | v27.59,31.31 32.16,31.31 v40.77,39.92
AD3  (via drill 0.61)
  Top 0.254: v72.01,33.59 71.33,32.91 70.26,32.91 IC1.67 | v75.44,30.77 v75.44,33.59 | v18.37,41.75 18.37,43.65 18.22,43.8 IC2.17 | v20.35,37.18 26.83,30.7 26.83,29.78 26.14,29.1 IC4.8
  Bottom 0.254: v75.44,33.59 v72.01,33.59 | v75.44,30.77 75.44,30.24 66.76,21.55 62.79,21.55 55.86,14.62 25,14.62 19.06,20.56 19.06,22.62 16.54,25.14 16.54,39.92 v18.37,41.75 18.83,41.82 20.35,40.3 v20.35,37.18
AD4  (via drill 0.61)
  Top 0.254: v71.48,36.41 71.48,34.43 70.49,33.44 70.26,33.44 IC1.66 | v58.45,61.86 57.54,62.78 21.11,62.78 17.38,59.04 17.38,53.86 v18.37,52.87 | v18.83,46.7 18.83,46.09 18.98,45.94 IC2.18 | v25.61,16.37 25.61,17.06 IC4.13
  Bottom 0.254: v71.48,36.41 71.48,48.83 v58.45,61.86 | v18.37,52.87 18.37,47.16 v18.83,46.7 19.06,46.24 21.19,44.11 21.19,20.49 25.3,16.37 v25.61,16.37
AD5  (via drill 0.61)
  Top 0.254: v68.13,33.9 69.04,33.9 IC1.65 | v65.92,35.12 55.78,35.12 v52.43,38.47 | v49.54,35.57 46.18,35.57 v41.53,30.93 | v26.83,20.72 26.83,19.04 IC4.14 | v25.99,30.16 18.67,37.48 18.67,40.76 20.27,42.36 20.27,43.8 IC2.19
  Bottom 0.254: v68.13,33.9 67.14,33.9 v65.92,35.12 | v49.54,35.57 v52.43,38.47 | v41.53,30.93 36.73,26.13 34.22,26.13 32.39,24.3 | 32.39,24.3 28.81,20.72 v26.83,20.72 | v25.99,30.16 26.52,30.16 32.39,24.3
AD6  (via drill 0.61)
  Top 0.254: v70.64,38.01 70.64,34.58 70.49,34.43 70.26,34.43 IC1.64 | v37.42,61.94 v57.23,61.94 | v20.58,46.85 21.49,45.94 IC2.20 21.49,43.8 21.49,42.97 19.51,40.99 v19.51,39.99 | v29.42,15.84 30.64,17.06 IC4.17
  Bottom 0.254: v70.64,38.01 70.64,48.53 v57.23,61.94 | v37.42,61.94 36.89,61.94 36.35,62.47 24.01,62.47 20.58,59.04 v20.58,46.85 | v29.42,15.84 26.83,15.84 26.07,15.08 25.15,15.08 20.2,20.03 20.2,25.29 19.51,25.97 v19.51,39.99
AD7  (via drill 0.61)
  Top 0.254: v56.09,27.12 60.2,27.12 67.98,34.89 69.04,34.89 IC1.63 | v45.04,24.3 42.37,24.3 39.71,21.63 v35.97,21.63 | v33.3,19.8 32.54,19.04 IC4.18 | v36.81,24.75 36.81,31.92 27.44,41.29 25.99,41.29 23.47,43.8 23.32,43.8 IC2.21
  Bottom 0.254: v56.09,27.12 54.49,27.12 53.42,26.05 46.79,26.05 v45.04,24.3 | v33.3,19.8 35.13,21.63 v35.97,21.63 36.2,22.09 36.2,23.08 36.81,23.69 v36.81,24.75
AD8  (via drill 0.61)
  Top 0.254: 72.93,25.52 73,25.44 73,25.21 IC1.4 | v64.39,25.52 72.93,25.52 | v53.57,25.21 53.57,25.97 52.35,27.19 IC5.3 | v66.45,55.08 65.31,55.08 62.87,52.64 50.07,52.64 46.18,56.53 IC3.13 | v81.69,41.21 v81.69,45.1 | 72.93,25.52 v73.31,25.9
  Bottom 0.254: v64.39,25.52 56.24,25.52 55.94,25.21 v53.57,25.21 | v66.45,55.08 76.43,45.1 v81.69,45.1 | v81.69,41.21 84.05,38.85 84.05,38.24 73.31,27.5 v73.31,25.9
AD9  (via drill 0.61)
  Top 0.254: 72.4,23.61 72.55,23.76 72.55,23.99 IC1.3 | v62.49,23.61 72.4,23.61 | v52.35,25.21 52.35,26.35 51.52,27.19 IC5.4 | v63.25,51.88 49.76,51.88 45.12,56.53 44.89,56.53 IC3.14 | v74.6,27.12 v74.6,32.76 | v72.47,23.23 72.47,23.54 72.4,23.61
  Bottom 0.254: v62.49,23.61 60.74,23.61 59.29,25.06 56.39,25.06 55.71,24.37 53.19,24.37 v52.35,25.21 | v63.25,51.88 66.98,48.15 66.98,37.48 71.71,32.76 v74.6,32.76 | v74.6,27.12 74.6,25.36 v72.47,23.23
AD10  (via drill 0.61)
  Top 0.254: v65.77,26.89 66.91,26.89 67.44,27.42 69.04,27.42 IC1.78 | v57.84,24.22 58.6,24.98 59.06,24.98 60.97,26.89 v61.12,26.89 v64.01,29.78 | v49.08,25.21 47.1,27.19 IC5.7 | v58.6,50.43 49.92,50.43 43.82,56.53 43.67,56.53 IC3.15
  Bottom 0.254: v61.12,26.89 v65.77,26.89 | v57.84,24.22 57.31,24.22 57,23.92 50.37,23.92 v49.08,25.21 | v58.6,50.43 58.6,44.8 60.13,43.27 60.13,33.67 v64.01,29.78
AD11  (via drill 0.61)
  Top 0.254: v66.83,27.95 69.04,27.95 IC1.77 | v46.11,26.51 46.11,27.19 IC5.8 46.11,29.17 v46.11,29.94 | v42.07,42.51 42.07,43.73 IC3.17
  Bottom 0.254: v66.83,27.95 54.72,27.95 53.27,26.51 v46.11,26.51 | v42.07,42.51 42.07,33.97 v46.11,29.94
AD12  (via drill 0.61)
  Top 0.254: v71.02,28.18 70.79,28.41 70.26,28.41 IC1.76 | v47.17,19.88 46.41,19.12 IC5.13 | v43.29,42.51 43.29,43.73 IC3.18 | v41.53,32.15 v43.29,33.9 | v37.65,23.92 v37.65,28.26
  Bottom 0.254: v71.02,28.18 68.81,28.18 59.67,19.04 53.65,19.04 | 53.65,19.04 48.01,19.04 v47.17,19.88 | v43.29,33.9 v43.29,42.51 | v37.65,28.26 v41.53,32.15 | v37.65,23.92 36.81,23.08 36.81,22.09 37.88,21.02 40.62,21.02 46.03,15.61 53.12,15.61 53.65,16.14 53.65,19.04
AD13  (via drill 0.61)
  Top 0.254: v67.82,28.95 69.04,28.95 IC1.75 | v60.13,28.95 51.67,37.4 v46.72,37.4 | v44.96,42.97 44.96,43.65 44.89,43.73 IC3.19 | v46.41,16.45 47.1,17.13 IC5.14 | v38.79,24.83 v38.79,30.62
  Bottom 0.254: v60.13,28.95 v67.82,28.95 | v46.72,37.4 44.96,39.16 v44.96,42.97 44.66,43.35 41.76,43.35 41.23,42.81 41.23,42.2 41.61,41.82 41.61,39.61 38.79,36.79 v38.79,30.62 | v46.41,16.45 45.8,16.45 38.79,23.46 v38.79,24.83
AD14  (via drill 0.61)
  Top 0.254: v71.02,29.4 70.26,29.4 IC1.74 | v52.28,19.88 51.52,19.12 IC5.17 | v46.18,42.51 46.18,43.73 IC3.20 | v46.18,39.08 47.02,38.24 v49.92,38.24 | v52.43,40.76 57.99,40.76 v62.79,35.96
  Bottom 0.254: 70.11,29.4 69.42,29.4 61.04,21.02 53.42,21.02 v52.28,19.88 | 70.11,29.4 v71.02,29.4 | v46.18,39.08 v46.18,42.51 | v52.43,40.76 v49.92,38.24 | v62.79,35.96 63.33,35.96 68.36,30.93 68.66,30.93 70.11,29.48 70.11,29.4
AD15  (via drill 0.61)
  Top 0.254: 68.36,29.94 67.67,29.94 59.06,21.33 59.06,19.65 55.02,15.61 52.51,15.61 51.97,16.14 51.97,16.91 52.2,17.13 IC5.18 | 68.36,29.94 69.04,29.94 IC1.73 | v47.4,42.89 47.4,43.73 IC3.21 | v47.4,39.08 50.68,39.08 56.62,33.14 v63.86,33.14 | 68.36,29.94 v68.36,30.09
  Bottom 0.254: v47.4,39.08 v47.4,42.89 | v63.86,33.14 66.91,30.09 v68.36,30.09
ALE  (via drill 0.61)
  Top 0.254: v61.73,29.78 67.37,35.42 69.04,35.42 IC1.62 | v42.68,23.46 42.14,23.46 39.71,21.02 37.27,21.02 36.81,20.56 36.81,19.57 37.27,19.12 43.29,19.12 IC5.11 | v23.55,19.88 23.55,19.04 IC4.11
  Bottom 0.254: v61.73,29.78 55.94,29.78 53.5,27.35 45.8,27.35 44.05,25.59 | 44.05,25.59 42.68,24.22 v42.68,23.46 | v23.55,19.88 30.79,19.88 36.58,25.67 43.97,25.67 44.05,25.59
B4  (via drill 0.61)
  Top 0.254: v74.76,36.41 74.53,36.64 74.53,37.18 IC1.54 | v62.49,64.38 v62.49,55.54 | v61.35,65.52 21.95,65.52 v12.58,56.15
  Bottom 0.254: v74.76,36.41 72.62,36.41 71.79,35.57 71.18,35.57 67.44,39.31 67.44,50.59 v62.49,55.54 | v61.35,65.52 v62.49,64.38 | v12.58,56.15 12.58,54.32 9.83,51.58 8.69,51.58 7.93,50.81 SV2.35
B5  (via drill 0.61)
  Top 0.254: v75.67,48.07 75.67,43.96 74.83,43.12 74.83,39.23 74.99,39.08 74.99,38.39 IC1.53
  Bottom 0.254: v75.67,48.07 74.83,48.91 74.83,49.67 60.28,64.23 56.85,64.23 56.09,64.99 22.03,64.99 14.33,57.29 14.33,53.02 12.2,50.89 10.44,50.89 SV2.36
C0  (via drill 0.61)
  Top 0.254: v90.61,28.34 85.04,33.9 83.52,33.9 IC1.36 | v92.05,26.89 92.36,26.89 93.81,25.44 96.47,25.44 97.46,26.43 102.42,26.43 105.31,23.54 105.31,13.1 98.15,5.93 98.15,5.63 93.73,1.21 16.54,1.21 14.33,3.42 5.26,3.42 2.14,6.54 2.14,33.21 v3.51,34.58
  Bottom 0.254: v92.05,26.89 v90.61,28.34 | v3.51,34.58 6.25,34.58 6.63,34.97 SV2.23
C1  (via drill 0.61)
  Top 0.254: v84.36,19.19 87.94,22.77 87.94,30.39 84.89,33.44 83.52,33.44 IC1.35 | v48.93,4.94 15.7,4.94 14.79,5.86 6.1,5.86 4.27,7.69 4.27,29.71 3.97,30.01 3.97,31.92 v5.42,33.37
  Bottom 0.254: v84.36,19.19 83.9,19.19 82.61,17.9 82.61,15.15 79.33,11.88 74.68,11.88 67.75,4.94 v48.93,4.94 | v5.42,33.37 6.41,33.37 7.32,34.28 8.46,34.28 9.15,34.97 SV2.24
C2  (via drill 0.61)
  Top 0.254: v85.43,39.38 80.85,39.38 80.02,38.55 80.02,38.39 IC1.43 | v91.52,49.29 91.52,51.42 92.05,51.96 92.05,56.68 88.17,60.57 86.34,60.57 82.3,64.61 82.3,64.91 80.85,66.36 16.54,66.36 5.42,55.23 v5.42,39.99
  Bottom 0.254: v85.43,39.38 90.84,44.8 90.84,46.85 91.22,46.85 91.22,49.29 v91.52,49.29 | v5.42,39.99 6.94,38.47 SV2.25
C5  (via drill 0.61)
  Top 0.254: v79.33,49.44 80.47,48.3 80.47,47.69 78.57,45.79 78.57,38.39 IC1.46
  Bottom 0.254: v79.33,49.44 78.49,49.44 70.72,57.22 68.51,57.22 59.82,65.9 16.08,65.9 6.25,56.07 6.25,50.05 7.32,48.99 7.78,48.99 8.31,48.45 8.31,45.02 7.24,43.96 6.79,43.96 6.25,43.42 6.25,39.92 7.32,38.85 8.46,38.85 9.15,38.17 SV2.26
F0  (via drill 0.61)
  Top 0.254: v81.23,27.04 82.07,27.88 82.22,27.88 IC1.24 | v80.85,22.7 80.85,19.5 78.49,17.13 76.59,17.13 73.61,14.16 73.61,10.81 v64.85,2.05
  Bottom 0.254: v81.23,27.04 81.23,23.08 v80.85,22.7 | v64.85,2.05 51.06,2.05 50.3,1.28 13.57,1.28 7.85,7 SV2.1
F1  (via drill 0.61)
  Top 0.254: v84.36,15.84 84.36,17.74 83.52,18.58 83.52,19.5 83.9,19.88 83.9,27.19 83.67,27.42 83.52,27.42 IC1.23
  Bottom 0.254: v84.36,15.84 84.36,15.08 72.17,2.89 51.29,2.89 50.14,1.74 13.72,1.74 10.14,5.32 10.14,6.7 SV2.2
F2  (via drill 0.61)
  Top 0.254: v80.02,21.86 80.02,23.99 IC1.18 | v25.76,12.94 10.83,12.94 10.29,13.48 6.79,13.48 6.25,12.94 6.25,11.34 7.02,10.58 SV2.3
  Bottom 0.254: v80.02,21.86 73.46,21.86 71.02,19.42 62.03,19.42 55.55,12.94 v25.76,12.94
F3  (via drill 0.61)
  Top 0.254: v78.19,17.97 78.95,18.73 78.95,21.94 79.48,22.47 79.48,23.99 IC1.17
  Bottom 0.254: v78.19,17.97 77.65,17.97 75.6,15.92 72.85,15.92 60.69,8.83 6.13,8.83 10.44,9.59 SV2.4
F4  (via drill 0.61)
  Top 0.254: v78.11,19.65 78.11,21.71 79.02,22.62 79.02,23.99 IC1.16 | v14.03,10.89 9.15,10.89 7.93,12.11 SV2.5
  Bottom 0.254: v78.11,19.65 75.29,16.83 71.63,16.83 64.55,9.74 15.17,9.74 v14.03,10.89
F5  (via drill 0.61)
  Top 0.254: v76.89,19.65 76.89,21.1 78.49,22.7 78.49,23.99 IC1.15 | v13.95,12.11 10.44,12.11 SV2.6
  Bottom 0.254: v76.89,19.65 73.84,19.65 64.39,10.2 15.85,10.2 v13.95,12.11
F6  (via drill 0.61)
  Top 0.254: v78.03,25.9 78.03,25.21 IC1.14 | v63.25,20.72 61.42,20.72 46.18,5.48 17.45,5.48 12.96,9.97 v11.21,9.97
  Bottom 0.254: v78.03,25.9 76.28,25.9 71.1,20.72 v63.25,20.72 | v11.21,9.97 9.76,11.42 9.3,11.42 8.31,12.41 8.31,13.55 7.55,14.32 SV2.7
F7  (via drill 0.61)
  Top 0.254: v76.89,23.15 77.5,23.76 77.5,23.99 IC1.13 | v24.92,13.78 14.03,13.78 13.19,14.62 10.44,14.62 SV2.8
  Bottom 0.254: v76.89,23.15 74.15,23.15 70.87,19.88 61.88,19.88 55.78,13.78 v24.92,13.78
G0  (via drill 0.61)
  Top 0.254: v61.42,11.04 73.54,23.15 73.54,23.99 IC1.5 | v14.79,20.49 v18.29,16.98 | v14.79,32.6 v11.66,35.73
  Bottom 0.254: v61.42,11.04 24.24,11.04 v18.29,16.98 | v14.79,20.49 v14.79,32.6 | v11.66,35.73 11.66,39.99 9.76,41.9 8.62,41.9 7.93,42.59 SV2.29
G1  (via drill 0.61)
  Top 0.254: v75.67,28.72 75.67,27.04 74.07,25.44 74.07,25.21 IC1.6 | v86.57,44.57 86.57,49.82 86.03,50.36 v86.03,51.35 | v86.64,53.18 86.64,55.46 83.67,58.43 78.26,58.43 71.48,65.22 62.18,65.22 60.2,63.24 20.73,63.24 15.78,58.28 v15.78,52.87
  Bottom 0.254: v75.67,28.72 75.67,29.25 84.59,38.17 84.59,42.89 86.26,44.57 v86.57,44.57 | v86.03,51.35 86.03,52.57 v86.64,53.18 | v15.78,52.87 15.78,49.21 10.14,43.58 SV2.30
G2  (via drill 0.61)
  Top 0.254: v4.58,42.43 4.58,34.51 3.51,33.44 3.51,29.86 3.82,29.56 3.82,7.53 5.95,5.4 14.64,5.4 15.93,4.1 55.63,4.1 74.53,23 74.53,23.99 IC1.7
  Bottom 0.254: v4.58,42.43 6.94,44.8 SV2.31
G3  (via drill 0.61)
  Top 0.254: v64.93,11.88 74.99,21.94 74.99,23.99 IC1.8 | v18.22,18.2 v18.22,22.32 | v15.63,33.44 11.28,37.78 11.28,43.65 10.14,44.8 SV2.32
  Bottom 0.254: v64.93,11.88 55.78,11.88 55.48,11.57 24.85,11.57 v18.22,18.2 | v18.22,22.32 18.22,22.85 15.63,25.44 v15.63,33.44
G4  (via drill 0.61)
  Top 0.254: v67.44,5.78 73.16,11.5 73.16,14.32 76.05,17.21 76.05,23.99 IC1.10 | v15.47,6.31 6.79,6.31 v5.11,7.99
  Bottom 0.254: v67.44,5.78 43.59,5.78 43.29,5.48 16.31,5.48 v15.47,6.31 | v5.11,7.99 5.11,25.97 2.14,28.95 2.14,42.43 7.02,47.31 SV2.33
GND  (via drill 0.61)
  Top 0.254: 86.95,17.74 86.64,17.74 C16.2 | 86.95,17.74 88.85,17.74 90,18.89 90.15,18.89 IC7.15 90.76,18.89 96.02,13.63 100.51,13.63 X1.5 | C8.2 76.13,14.39 76.13,9.82 76.66,9.29 79.86,9.29 84.59,14.01 86.49,14.01 86.95,14.47 86.95,17.74 | C7.2 63.56,51.04 69.27,56.76 69.27,57.52 C1.2 | IC9.4 90.61,56 90.61,55.23 IC9.3 90.61,54.7 90.61,53.94 IC9.2 90.61,53.48 90.61,52.72 IC9.1 90.15,52.19 90.15,51.12 C17.2 | 8.31,53.1 9.15,53.1 SV2.38 | 8.31,53.1 7.93,53.1 SV2.37 | 8.31,53.1 8.31,42.43 7.55,41.67 7.55,41.06 SV2.27 SV2.28 10.06,39.69 10.06,39.08 10.83,38.32 10.83,25.44 | SV2.10 SV2.9 7.55,18.2 7.55,18.81 8.31,19.57 8.31,25.14 | 10.83,25.44 10.44,25.44 SV2.16 8.31,25.14 | 10.83,25.44 20.66,25.44 22.33,27.12 23.02,27.12 IC4.10 23.63,27.12 23.78,27.12 24.08,26.81 30.18,26.81 30.33,26.96 30.33,29.33 30.49,29.48 32.69,29.48 32.85,29.33 32.85,26.96 33,26.81 35.06,26.81 | 8.31,25.14 SV2.15 | 32.31,54.17 35.67,50.81 38.41,50.81 C6.2 39.32,51.12 41.84,53.63 41.84,56.53 IC3.16 | 32.31,54.17 30.03,56.45 30.03,58.97 29.88,59.12 29.8,59.12 27.82,61.1 20.05,61.1 18.22,59.27 18.22,58.74 IC2.16 | 35.06,26.81 35.06,25.36 37.34,23.08 C3.2 38.33,22.93 40.39,22.93 43.29,25.82 43.29,27.19 IC5.10 43.9,29.17 43.9,30.09 44.58,30.77 54.03,30.77 54.72,30.09 54.72,29.17 IC5.1 55.02,27.19 55.02,25.9 57.76,23.15 C4.2 58.68,22.85 59.36,22.85 67.9,31.38 69.04,31.38 IC1.70 70.26,31.46 71.02,31.46 75.18,35.61 | 35.06,26.81 35.06,27.12 IC4.1 34.45,29.1 34.45,31.46 33.08,32.83 v33.08,33.37 | v76.51,27.04 76.51,25.21 IC1.11 | IC1.26 82.22,28.95 v81.39,28.95 81.16,29.4 80.7,29.86 80.7,30.7
  Top 0.254: 80.7,30.7 81.39,31.38 82.22,31.38 IC1.31 | 75.18,35.61 76.05,36.49 76.05,37.18 IC1.51 | 80.7,30.7 80.62,30.77 80.02,30.77 75.18,35.61 | v30.87,52.72 32.31,54.17
  Bottom 0.254: C13.- 97.46,6.7 97.46,9.06 100.97,12.56 X1.5 101.58,14.01 103.94,16.37 104.32,16.37 105.39,17.44 105.39,35.3 | 100.47,36.07 96.17,31.76 SV1.3 93.65,31.76 93.12,31.76 92.28,32.6 82.61,32.6 80.7,30.7 80.7,28.34 80.78,28.26 | C9.2 84.05,43.19 88.47,47.61 88.7,47.84 | C2.2 75.21,58.43 76.43,59.65 76.66,59.88 | C1.2 70.11,58.43 73.84,62.17 74.11,62.44 | v76.51,27.04 77.73,27.04 77.96,26.81 79.33,26.81 80.78,28.26 | 80.78,28.26 81.39,28.87 v81.39,28.95 | v30.87,52.72 30.56,52.72 27.51,49.67 27.21,49.67 26.68,49.14 26.68,42.66 33.08,36.26 v33.08,33.37
  pour Bottom: 69.5,67.05 107.6,67.05 107.6,35.3 101.25,35.3
INT0  (via drill 0.61)
  Top 0.254: v73.92,35.57 72.55,36.95 72.55,37.18 IC1.58 | v81.92,37.25 85.73,37.25 v92.28,30.7
  Bottom 0.254: v73.92,35.57 78.11,35.57 79.79,37.25 v81.92,37.25 | v92.28,30.7 89.92,30.7 87.79,28.56 87.79,27.27 83.9,23.38 83.29,23.38 80.4,20.49 73.39,20.49 65.61,12.71 56.01,12.71 55.33,12.03 25.53,12.03 18.52,19.04 8.62,19.04 7.93,19.73 SV2.11
INT1  (via drill 0.61)
  Top 0.254: v72.32,41.67 73,40.99 73,38.39 IC1.57 | v72.32,43.96 72.7,43.96 74.83,46.09 74.83,48.45 v75.67,49.29 | v13.49,53.33 13.49,36.72 v13.8,36.41
  Bottom 0.254: v72.32,43.96 v72.32,41.67 | v75.67,49.29 75.67,49.44 59.67,65.45 21.87,65.45 13.49,57.06 v13.49,53.33 | v13.8,36.41 13.8,24.37 10.14,20.72 SV2.12
INT2  (via drill 0.61)
  Top 0.254: v73.16,42.51 73.54,42.13 73.54,38.39 IC1.56 | v73.16,47.23 73.16,49.52 v71.63,51.04
  Bottom 0.254: v73.16,47.23 v73.16,42.51 | v71.63,51.04 59.36,63.31 52.89,63.31 52.81,63.39 22.33,63.39 17.07,58.13 17.07,41.67 12.96,37.56 12.96,28.56 10.52,26.13 9.3,26.13 8.31,25.14 8.31,23.92 7.63,23.23 SV2.13
INT3  (via drill 0.61)
  Top 0.254: v74,43.35 74,38.39 IC1.55 | v74,49.21 v74,46.4 | v11.82,26.28 v11.82,28.56
  Bottom 0.254: v74,46.4 v74,43.35 | v74,49.21 74,49.9 60.13,63.77 54.64,63.77 54.26,64.15 22.26,64.15 16.62,58.51 16.62,41.82 12.5,37.71 12.5,29.25 v11.82,28.56 | v11.82,26.28 11.82,24.91 10.14,23.23 SV2.14
N$2
  Top 0.254: IC1.50 76.51,38.39 76.51,49.6 72.4,53.71 Q1.1 72.09,54.93 72.09,57.52 C1.1
N$3
  Top 0.254: IC1.49 77.04,38.39 77.04,53.71 Q1.2 77.12,54.93 C2.1
N$4
  Top 0.254: R1.1 LED1.A
N$5
  Top 0.254: IC7.1 88.93,9.13 88.32,9.13 85.58,6.39 C14.+
N$6  (via drill 0.61)
  Top 0.254: v92.28,29.48 86.87,34.89 83.52,34.89 IC1.38 | v97.77,25.59 97.77,20.87 IC7.9
  Bottom 0.254: v92.28,29.48 94.42,27.35 96.02,27.35 v97.77,25.59
N$7  (via drill 0.61)
  Top 0.254: v90.23,29.86 85.65,34.43 83.52,34.43 IC1.37 | v91.29,25.97 96.55,20.72 IC7.10
  Bottom 0.254: v90.23,29.86 90.23,29.1 89.77,28.64 89.77,27.5 v91.29,25.97
N$8
  Top 0.254: IC7.14 91.98,18.89 92.21,18.89 96.09,15 101.81,15 103.48,16.68 X1.8
N$9  (via drill 0.61)
  Top 0.254: v98.38,12.79 98.38,11.04 IC7.8
  Bottom 0.254: v98.38,12.79 98.38,15.46 100.97,18.05 X1.3
N$10
  Top 0.254: IC7.7 97.08,9.13 97.24,9.13 97.62,8.75 99.45,8.75 104.86,14.16 104.86,23.38 104.25,23.99 103.33,23.99 101.58,22.24 X1.2
N$11
  Top 0.254: X1.4 101.58,16.75 101.58,17.59 102.72,18.73 102.72,21.4 103.48,22.16 X1.6
N$12
  Top 0.254: IC7.3 91.45,11.04 91.29,11.04 90.91,11.42 90,11.42 89.84,11.27 89.84,8.9 C14.-
N$13  (via drill 0.61)
  Top 0.254: v93.96,21.55 93.27,20.87 IC7.13
  Bottom 0.254: v93.96,21.55 99.67,21.55 100.74,20.49 103.1,20.49 X1.7
N$14
  Top 0.254: IC7.4 92.74,11.04 92.59,11.04 91.75,11.88 85.35,11.88 C15.+
N$15
  Top 0.254: IC7.5 93.96,11.04 91.83,13.17 84.36,13.17 83.75,12.56 83.75,11.42 84.43,10.73 C15.-
N$16
  Top 0.254: IC7.2 90.76,9.13 90.76,7.76 91.83,6.7 C12.+
N$17
  Top 0.305: D1.A 96.55,51.04 96.55,46.47 J1.1
N$18
  Top 0.305: C10.+ 100.44,56.38 100.44,61.71 IC8.1 99.22,62.02 96.93,62.02 D1.C
N$19
  Top 0.254: IC7.6 95.41,9.13 95.41,6.7 C13.+
N$20
  Top 0.254: R4.1 91.45,62.4 91.45,60.04 D2.A
N$22  (via drill 0.61)
  Top 0.254: v75.67,39.54 75.52,39.38 75.52,38.39 IC1.52 | v83.22,38.55 91.98,38.55 93.65,36.87 SV1.1
  Bottom 0.254: v75.67,39.54 82.22,39.54 v83.22,38.55
N$23  (via drill 0.61)
  Top 0.254: v85.43,36.41 81.62,36.41 81.31,36.72 78.26,36.72 78.03,36.95 78.03,37.18 IC1.47
  Bottom 0.254: v85.43,36.41 91.6,36.41 93.65,34.36 SV1.2
N$24  (via drill 0.61)
  Top 0.254: S1.2 81.54,63.77 81.54,60.04 D2.C 83.44,59.12 83.6,59.12 88.85,53.86 88.85,50.05 89.77,49.14 v90.3,49.14 | v72.32,12.94 72.32,14.09 75.52,17.29 75.52,23.99 IC1.9 | v90.3,47.46 90.3,47 99.67,37.63 99.67,30.93 95.79,27.04 SV1.5
  Bottom 0.254: v72.32,12.94 78.41,12.94 81.69,16.22 81.69,18.81 85.27,22.39 88.85,22.39 92.59,26.13 93.65,26.13 SV1.5 | v90.3,47.46 v90.3,49.14
RA0  (via drill 0.61)
  Top 0.254: v30.26,35.04 33.3,31.99 33.3,29.1 IC4.2 | v23.09,55.46 23.09,56.61 IC2.12 23.02,58.74 v23.7,59.43 | v37.65,59.43 45.95,59.43 46.72,58.66 46.94,58.66 IC3.12
  Bottom 0.254: v30.26,35.04 23.78,41.52 23.78,54.78 v23.09,55.46 | v23.7,59.43 v37.65,59.43
RA1  (via drill 0.61)
  Top 0.254: v27.13,40.45 29.42,38.17 29.42,29.1 IC4.5 | v24.31,55.46 24.31,56.61 IC2.11 24.62,58.74 v26.14,60.26 | v47.4,59.43 48.16,58.66 IC3.11 | v31.25,61.1 v45.73,61.1
  Bottom 0.254: v27.13,40.45 27.13,40.99 24.31,43.8 v24.31,55.46 | v45.73,61.1 v47.4,59.43 | v31.25,61.1 30.87,61.1 29.65,59.88 26.52,59.88 v26.14,60.26
RA2  (via drill 0.61)
  Top 0.254: v28.43,38.01 28.43,29.1 IC4.6 | v25.53,55.46 25.53,56.61 IC2.10 | v48.39,55.46 49.46,56.53 IC3.10
  Bottom 0.254: v28.43,38.01 28.43,40.3 25.3,43.42 25.3,55.23 v25.53,55.46 25.99,55.54 26.9,55.54 26.98,55.46 v48.39,55.46
RA3  (via drill 0.61)
  Top 0.254: v26.14,52.57 23.55,52.57 17.38,46.4 17.38,38.17 24.62,30.93 24.62,29.1 IC4.9 | v26.6,54.7 26.6,56.61 IC2.9 | v49.61,55.39 50.75,56.53 IC3.9
  Bottom 0.254: v26.14,52.57 26.14,54.24 v26.6,54.7 27.06,54.62 48.7,54.62 49.46,55.39 v49.61,55.39
RA4  (via drill 0.61)
  Top 0.254: v19.36,24.07 20.5,24.07 24.39,20.18 24.39,19.04 IC4.12 | v18.22,36.18 18.22,36.72 16.92,38.01 16.92,46.7 21.87,51.65 v21.87,52.19 | v21.87,54.24 25.91,54.24 26.29,53.86 26.9,53.86 27.82,54.78 | 27.82,54.78 27.89,54.85 27.89,56.61 IC2.8 | v51.67,55.39 51.97,55.69 51.97,56.53 IC3.8 | 27.82,54.78 v28.81,53.79
  Bottom 0.254: v19.36,24.07 19.36,25.52 18.22,26.66 v18.22,36.18 | v21.87,52.19 v21.87,54.24 | v51.67,55.39 50.68,54.4 49.92,54.4 49.54,54.02 29.04,54.02 v28.81,53.79
RA5  (via drill 0.61)
  Top 0.254: v24.01,24.68 28.12,20.56 28.12,19.04 IC4.15 | v22.94,46.7 v28.28,52.03 | v29.65,52.95 29.65,56.23 29.27,56.61 IC2.7 | v51.82,53.94 53.27,55.39 53.27,56.53 IC3.7
  Bottom 0.254: v24.01,24.68 24.01,29.25 22.94,30.32 v22.94,46.7 | v28.28,52.03 28.73,52.03 v29.65,52.95 30.1,53.18 30.49,53.56 50.14,53.56 50.53,53.94 v51.82,53.94
RA6  (via drill 0.61)
  Top 0.254: v25.99,23.84 29.42,20.41 29.42,19.04 IC4.16 | v29.34,60.72 29.34,60.26 30.87,58.74 IC2.6 | v54.56,55.84 54.56,56.53 IC3.6
  Bottom 0.254: v25.99,23.84 23.7,23.84 22.1,25.44 22.1,51.27 22.71,51.88 22.71,54.7 22.26,55.16 22.26,56.3 | 22.26,56.3 22.26,59.12 24.24,61.1 28.96,61.1 v29.34,60.72 | v54.56,55.84 52.96,55.84 52.51,56.3 22.26,56.3
RA7  (via drill 0.61)
  Top 0.254: v32.31,16.37 33,17.06 33.23,17.06 IC4.19 | v30.1,61.64 30.1,61.1 31.7,59.5 31.7,58.74 IC2.5 | v55.02,59.43 55.78,58.66 IC3.5
  Bottom 0.254: v32.31,16.37 30.64,16.37 27.97,19.04 23.25,19.04 21.65,20.64 21.65,51.27 21.04,51.88 21.04,58.89 23.78,61.64 v30.1,61.64 30.49,61.94 36.28,61.94 39.63,58.59 47.71,58.59 48.54,59.43 v55.02,59.43
RA8  (via drill 0.61)
  Top 0.254: v53.73,29.94 53.73,29.17 IC5.2 | v54.49,42.97 54.49,43.65 54.56,43.73 IC3.27 54.56,45.86 52.74,47.69 43.13,47.69 37.95,42.51 32.39,42.51 31.09,43.8 30.94,43.8 IC2.27
  Bottom 0.254: v53.73,29.94 53.73,42.2 v54.49,42.97
RA9  (via drill 0.61)
  Top 0.254: v49.92,29.94 49.92,29.17 IC5.5 | v53.27,42.97 53.27,43.73 IC3.26 | v29.57,42.89 29.57,43.8 IC2.26 | v32.09,40.38 38.87,40.38 39.25,40.76 v49.76,40.76
  Bottom 0.254: v49.92,29.94 49.92,34.81 53.27,38.17 53.27,42.05 | 53.27,42.05 v53.27,42.97 | v32.09,40.38 v29.57,42.89 | v49.76,40.76 51.06,42.05 53.27,42.05
RA10  (via drill 0.61)
  Top 0.254: v48.7,29.94 48.7,29.17 IC5.6 | IC3.23 49.54,43.73 v49.54,42.36 49.08,42.13 48.16,41.21 28.66,41.21 26.07,43.8 25.84,43.8 IC2.23
  Bottom 0.254: v48.7,29.94 48.7,41.52 v49.54,42.36
RA11  (via drill 0.61)
  Top 0.254: v44.89,29.94 44.89,29.17 IC5.9 | v51.9,42.97 51.9,43.65 51.97,43.73 IC3.25 51.97,45.86 51.67,46.17 49.23,46.17 49.08,46.01 49.08,43.42 47.33,41.67 29.65,41.67 28.43,42.89 28.43,43.8 IC2.25
  Bottom 0.254: v44.89,29.94 45.73,29.1 46.41,29.1 48.24,30.93 48.24,42.2 49.23,43.19 51.67,43.19 v51.9,42.97
RA12  (via drill 0.61)
  Top 0.254: v45.12,19.88 45.12,19.12 IC5.12 | v40.7,24.37 40.7,38.78 v39.55,39.92 | v38.03,52.03 33.46,56.61 IC2.4 | v54.79,53.48 57.08,55.77 57.08,56.53 IC3.4
  Bottom 0.254: v45.12,19.88 40.7,24.3 v40.7,24.37 | v39.55,39.92 39.55,44.72 39.02,45.25 39.02,46.62 38.03,47.61 v38.03,52.03 38.49,52.26 53.04,52.26 54.26,53.48 v54.79,53.48
RA13  (via drill 0.61)
  Top 0.254: v49,19.88 49,19.12 IC5.15 | v49,23.99 50.6,25.59 50.6,29.4 v51.14,29.94 | v52.89,31.69 v54.56,33.37 | v56.09,46.55 56.09,45.86 IC3.28 | v39.86,45.56 37.27,42.97 33.23,42.97 32.39,43.8 32.24,43.8 IC2.28
  Bottom 0.254: v49,19.88 v49,23.99 | v51.14,29.94 v52.89,31.69 | v54.56,33.37 54.56,41.75 56.09,43.27 56.09,45.56 | 56.09,45.56 v56.09,46.55 | 56.09,45.56 v39.86,45.56
RA14  (via drill 0.61)
  Top 0.254: v50.22,19.88 50.22,19.12 IC5.16 | v53.04,22.7 53.04,23.54 54.41,24.91 54.41,25.75 53.12,27.04 53.12,29.4 52.58,29.94 v52.51,29.94 | v57.76,55.31 57.76,55.92 58.37,56.53 IC3.3 | v41.08,57.14 40.24,56.3 35.29,56.3 34.98,56.61 34.75,56.61 IC2.3
  Bottom 0.254: v50.22,19.88 v53.04,22.7 | v52.51,29.94 53.35,29.1 54.03,29.1 57,32.07 57,49.44 57.76,50.21 v57.76,55.31 57.31,55.54 55.71,57.14 v41.08,57.14
RA15  (via drill 0.61)
  Top 0.254: v52.81,16.45 53.5,17.13 IC5.19 | v39.63,23.76 39.63,26.35 v39.86,26.58 39.63,27.04 39.63,30.93 36.66,33.9 v36.66,36.95 | v59.21,43.04 59.9,43.73 IC3.31 | v31.09,42.51 30.03,43.58 30.03,46.09 31.48,47.54 32.69,47.54 33.84,46.4 33.84,43.65 34.07,43.42 34.9,43.42 35.29,43.8 35.51,43.8 IC2.31
  Bottom 0.254: v52.81,16.45 48.39,16.45 45.8,19.04 44.35,19.04 v39.63,23.76 | v39.86,26.58 44.43,26.58 46.49,28.64 54.18,28.64 57.46,31.92 57.46,41.29 v59.21,43.04 | v36.66,36.95 v31.09,42.51
SCK  (via drill 0.61)
  Top 0.254: IC1.44 79.56,38.39 79.56,44.11 81.31,45.86 R2.1 82.83,47.39 v83.44,48 | v82.22,53.1 82.22,53.86 82.91,54.55 82.91,54.7 IC9.6
  Bottom 0.254: v82.22,53.1 82.22,49.21 v83.44,48
SDI  (via drill 0.61)
  Top 0.254: IC1.45 79.02,38.39 79.02,45.63 80.93,47.54 80.93,48 81.31,48.38 R3.1 82,50.13 v81.23,50.89 | v81.23,54.32 82.91,56 IC9.5
  Bottom 0.254: v81.23,50.89 v81.23,54.32

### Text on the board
tNames: PIC18F8720 External Memory Testboard | (C) 03/05/2005 | by Daniel Porzig | www.base32.de.vu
